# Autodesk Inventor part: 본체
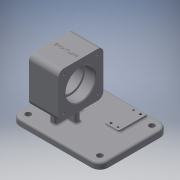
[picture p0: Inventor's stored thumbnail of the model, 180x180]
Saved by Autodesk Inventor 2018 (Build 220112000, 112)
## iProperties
Created: 2019-09
Part Number: 본체
Material: 알루미늄 6061
Document SubType Name: Modeling
Designer: mduedu
Density: 2.71 g/cm^3
Appearance: 기본값
Mass: 636.366 g
Surface Area: 520.125 cm^2
Volume: 234.821 cm^3
Author: mduedu
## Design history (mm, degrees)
sketch "스케치1"
  geometry: L1 (42, -62)-(-84, -62); L2 (-84, -62)-(-84, 36); L3 (-84, 36)-(42, 36); L4 (42, 36)-(42, -62); 1 further point
  constraints: 8 end point, 2 parallel, 1 horizontal, 1 perpendicular
  dimensions: "d0" = 36 distance from line of L3 point (0, 0); "d1" = 98 distance of L1.end L2.end; "d2" = 42 distance from line of L4 point (0, 0); "d3" = 126 distance of L2.end L3.end
extrude "돌출1" new body sketch "스케치1" distance "d4" = 9; taper "d5" = 0 deg
sketch "스케치2"
  geometry: L1 (0, -62)-(0, 36) reference; L2 (27, -32)-(91, -32); L3 (91, -32)-(91, 32); L4 (91, 32)-(27, 32); L5 (27, 32)-(27, -32); L6 (27, -32)-(91, 32); L7 (91, -32)-(27, 32); 3 further points
  constraints: 12 end point, 3 midpoint, 2 parallel, 1 horizontal, 1 horizontal alignment, 1 perpendicular
  dimensions: "d87" = 64 distance of L4.end L3.end; "d88" = 64 distance of L3.end L2.end; "d89" = 59 distance from line of point (59, 0) L1
extrude "돌출2" join sketch "스케치2" stored distance "d8" = 42; taper "d9" = 0 deg
sketch "스케치3"
  geometry: L1 (-17, 4)-(17, 4); L2 (17, 4)-(17, -4); L3 (17, -4)-(-17, -4); L4 (-17, -4)-(-17, 4); L5 (-4, 20)-(4, 20); L6 (4, 20)-(4, -20); L7 (4, -20)-(-4, -20); L8 (-4, -20)-(-4, 20); 5 further points
  constraints: 16 end point, 4 midpoint, 4 parallel, 2 horizontal, 2 horizontal alignment, 2 perpendicular, 2 vertical alignment
  dimensions: "d10" = 8 distance of L5.start L5.end; "d12" = 8 distance of L1.end L2.end; "d13" = 34 distance of L2.end L3.end; "d14" = 40 distance of L5.end L6.end
extrude "돌출3" join sketch "스케치3" stored distance "d15" = 42; taper "d16" = 0 deg
sketch "스케치4"
  geometry: L1 (-32, 91)-(-32, 27) reference; L2 (32, 91)-(-32, 91) reference; L3 (32, 27)-(32, 91) reference; L4 (-32, 27)-(32, 27) reference; C1 r 21 at (0, 59); 3 further points
  constraints: 2 midpoint, 1 centre point, 1 horizontal alignment, 1 vertical alignment
  dimensions: "d17" = 42 diameter of C1
extrude "돌출4" cut sketch "스케치4" distance "d18" = 15; taper "d19" = 0 deg
hole "구멍1" diameter "d22" = 36; stored, may be unused: countersink angle "d26" = 90 deg, drill point angle "d28" = 118 deg; dims "d20" = 10, "d21" = 10, "d23" = 6, "d24" = 4, "d25" = 2, "d27" = 8
fillet "모깎기1" dims "d29" = 0.3
chamfer "모따기1" distance "d30" = 1; stored, may be unused: second distance "d31" = 2, angle "d32" = 45 deg
fillet "모깎기9" dims "d90" = 8
sketch "스케치11"
  geometry: L1 (-24, 27)-(24, 27) reference; L2 (32, 35)-(32, 83) reference; L3 (24, 91)-(-24, 91) reference; L4 (-32, 83)-(-32, 35) reference; C1 r 22 at (0, 59) reference; A1 r 8 centre (-24, 35) between (-32, 35) and (-24, 27) reference; A2 r 8 centre (24, 35) between (24, 27) and (32, 35) reference; A3 r 8 centre (24, 83) between (32, 83) and (24, 91) reference; A4 r 8 centre (-24, 83) between (-24, 91) and (-32, 83) reference; 5 further points
  constraints: 4 coincident
hole "구멍6" sketch "스케치11" at (-24, 83), (24, 83), (24, 35), (-24, 35) diameter "d91" = 3.242; stored, may be unused: countersink angle "d95" = 90 deg, drill point angle "d97" = 118 deg; dims "d92" = 8, "d93" = 4, "d94" = 2, "d96" = 10
fillet "모깎기2" dims "d44" = 12
sketch "스케치6"
  geometry: L1 (-42, 50)-(-42, -24) reference; L2 (-30, -36)-(72, -36) reference; L3 (84, -24)-(84, 50) reference; L4 (72, 62)-(-30, 62) reference; L5 (17, 4)-(17, -4) reference; L6 (17, -4)-(4, -4) reference; L7 (4, -4)-(4, -20) reference; L8 (4, -20)-(-4, -20) reference; L9 (-4, -20)-(-4, -4) reference; L10 (-4, -4)-(-17, -4) reference; L11 (-17, -4)-(-17, 4) reference; L12 (-17, 4)-(-4, 4) reference; L13 (-4, 4)-(-4, 20) reference; L14 (-4, 20)-(4, 20) reference; L15 (4, 20)-(4, 4) reference; L16 (4, 4)-(17, 4) reference; A1 r 12 centre (-30, 50) between (-30, 62) and (-42, 50) reference; A2 r 12 centre (-30, -24) between (-42, -24) and (-30, -36) reference; A3 r 12 centre (72, -24) between (72, -36) and (84, -24) reference; A4 r 12 centre (72, 50) between (84, 50) and (72, 62) reference; 5 further points
  constraints: 4 coincident
hole "구멍3" sketch "스케치6" at (-30, 50), (72, 50), (72, -24), (-30, -24) diameter "d45" = 8; stored, may be unused: countersink angle "d49" = 90 deg, drill point angle "d51" = 118 deg; dims "d46" = 8, "d47" = 4, "d48" = 2, "d50" = 10
sketch "스케치7"
  geometry: L1 (38, 57)-(58, 57); L2 (58, 57)-(58, 17); L3 (58, 17)-(38, 17); L4 (38, 17)-(38, 57); L5 (72, 62)-(-30, 62) reference; 3 further points
  constraints: 8 end point, 2 midpoint, 2 parallel, 1 horizontal, 1 perpendicular
  dimensions: "d52" = 48 horizontal distance of point (48, 57) point (0, 0); "d53" = 20 distance of L1.start L1.end; "d54" = 40 distance of L1.end L2.end; "d55" = 25 distance from line of point (38, 37) L5
extrude "돌출5" join sketch "스케치7" distance "d56" = 3; taper "d57" = 0 deg
fillet "모깎기3" dims "d58" = 3
fillet "모깎기4" dims "d59" = 3
fillet "모깎기5" dims "d60" = 3
fillet "모깎기6" dims "d61" = 3
fillet "모깎기7" dims "d62" = 3
fillet "모깎기8" dims "d63" = 3
sketch "스케치8"
  geometry: L1 (72, 62)-(58.317, 62) reference; L2 (84, -24)-(84, 50) reference; C1 r 1.5 at (43, 53); C2 r 1.5 at (53, 21); 1 further point
  constraints: 2 centre point, 1 equal radius
  dimensions: "d64" = 3 diameter of C1; "d65" = 9 distance from line of C1.centre L1; "d66" = 32 vertical distance of C2.centre C1.centre; "d67" = 10 horizontal distance of C2.centre C1.centre; "d68" = 31 distance from line of L2 C2.centre
hole "구멍4" sketch "스케치8" at (43, 53), (53, 21) diameter "d69" = 3; stored, may be unused: countersink angle "d73" = 90 deg, drill point angle "d75" = 118 deg; dims "d70" = 8, "d71" = 4, "d72" = 2, "d74" = 6
sketch "스케치9"
  geometry: C1 r 1.5 at (43, 53) reference; C2 r 1.5 at (53, 21) reference; 3 further points
  constraints: 2 horizontal alignment, 2 vertical alignment
hole "구멍5" sketch "스케치9" at (53, 53), (43, 21) diameter "d76" = 3.242; stored, may be unused: countersink angle "d80" = 90 deg, drill point angle "d82" = 118 deg; dims "d77" = 6, "d78" = 4, "d79" = 2, "d81" = 8
sketch "스케치10"
  geometry: 2 further points
  constraints: 1 coincident, 1 other
feature "엠보싱1" sketch "스케치10" dims "d0" = 36, "d1" = 98, "d2" = 42, "d3" = 126, "d12" = 8, "d13" = 34, "d85" = 0.5, "d86" = 0
node "솔리드1"
mirror "대칭1"
mirror "대칭2"
node "투영된 루프1"
node "투영된 루프2"
